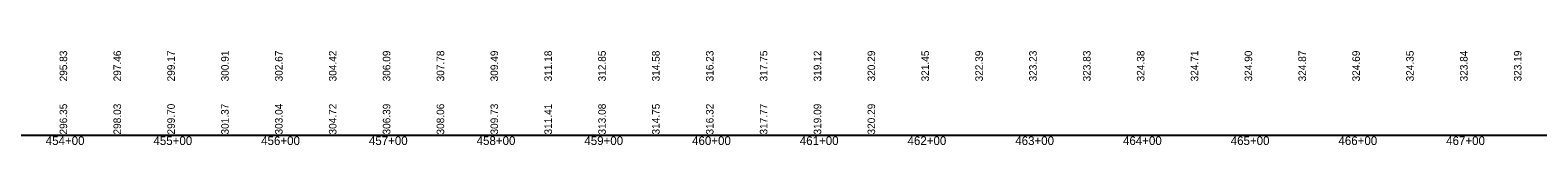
# Model space of a CAD drawing. Extents: x 1876258 to 1926563, y 729739 to 834437.
# Drawn here: x 1923728 to 1925127, y 830495 to 830583 of the extents above; entities that cross this region are included whole.
import ezdxf

# ---------------------------------------------------------------- set-up
doc = ezdxf.new("R2010")
doc.units = 0
for name, color, linetype in [('RD_EX_RailRoad', 7, 'Continuous'), ('RD_PD_ALT3_CL', 7, 'Continuous'), ('RD_PD_Final_Cl', 7, 'Continuous')]:
    doc.layers.add(name, color=color, linetype=linetype)

msp = doc.modelspace()

# ---------------------------------------------------------------- linework, layer by layer
at = {"layer": 'RD_PD_Final_Cl'}
msp.add_line((1878363.1, 830504.3), (1926563.1, 830504.3), dxfattribs=at)

# ---------------------------------------------------------------- texts
at = {"layer": 'RD_EX_RailRoad'}
for s, p in [('295.83', (1923762.1, 830554.3)), ('297.46', (1923812.1, 830554.3)), ('299.17', (1923862.1, 830554.3)), ('300.91', (1923912.1, 830554.3)), ('302.67', (1923962.1, 830554.3)), ('304.42', (1924012.1, 830554.3)), ('306.09', (1924062.1, 830554.3)), ('307.78', (1924112.1, 830554.3)), ('309.49', (1924162.1, 830554.3)), ('311.18', (1924212.1, 830554.3)), ('312.85', (1924262.1, 830554.3)), ('314.58', (1924312.1, 830554.3)), ('316.23', (1924362.1, 830554.3)), ('317.75', (1924412.1, 830554.3)), ('319.12', (1924462.1, 830554.3)), ('320.29', (1924512.1, 830554.3)), ('321.45', (1924562.1, 830554.3)), ('322.39', (1924612.1, 830554.3)), ('323.23', (1924662.1, 830554.3)), ('323.83', (1924712.1, 830554.3)), ('324.38', (1924762.1, 830554.3)), ('324.71', (1924812.1, 830554.3)), ('324.90', (1924862.1, 830554.3)), ('324.87', (1924912.1, 830554.3)), ('324.69', (1924962.1, 830554.3)), ('324.35', (1925012.1, 830554.3)), ('323.84', (1925062.1, 830554.3)), ('323.19', (1925112.1, 830554.3)), ('296.35', (1923762.1, 830505)), ('298.03', (1923812.1, 830505)), ('299.70', (1923862.1, 830505)), ('301.37', (1923912.1, 830505)), ('303.04', (1923962.1, 830505)), ('304.72', (1924012.1, 830505)), ('306.39', (1924062.1, 830505)), ('308.06', (1924112.1, 830505)), ('309.73', (1924162.1, 830505)), ('311.41', (1924212.1, 830505)), ('313.08', (1924262.1, 830505)), ('314.75', (1924312.1, 830505)), ('316.32', (1924362.1, 830505)), ('317.77', (1924412.1, 830505)), ('319.09', (1924462.1, 830505)), ('320.29', (1924512.1, 830505))]:
    msp.add_text(s, height=7, rotation=90, dxfattribs=at).set_placement(p)
at = {"layer": 'RD_PD_ALT3_CL'}
for s, p in [('454+00', (1923742.2, 830495.3)), ('454+00', (1923742.2, 830495.3)), ('455+00', (1923842.2, 830495.3)), ('455+00', (1923842.2, 830495.3)), ('456+00', (1923942.2, 830495.3)), ('456+00', (1923942.2, 830495.3)), ('457+00', (1924042.2, 830495.3)), ('457+00', (1924042.2, 830495.3)), ('458+00', (1924142.2, 830495.3)), ('458+00', (1924142.2, 830495.3)), ('459+00', (1924242.2, 830495.3)), ('459+00', (1924242.2, 830495.3)), ('460+00', (1924342.2, 830495.3)), ('460+00', (1924342.2, 830495.3)), ('461+00', (1924442.2, 830495.3)), ('461+00', (1924442.2, 830495.3)), ('462+00', (1924542.2, 830495.3)), ('462+00', (1924542.2, 830495.3)), ('463+00', (1924642.2, 830495.3)), ('463+00', (1924642.2, 830495.3)), ('464+00', (1924742.2, 830495.3)), ('464+00', (1924742.2, 830495.3)), ('465+00', (1924842.2, 830495.3)), ('465+00', (1924842.2, 830495.3)), ('466+00', (1924942.2, 830495.3)), ('466+00', (1924942.2, 830495.3)), ('467+00', (1925042.2, 830495.3)), ('467+00', (1925042.2, 830495.3))]:
    msp.add_text(s, height=8, dxfattribs=at).set_placement(p)

doc.saveas('drawing.dxf')
